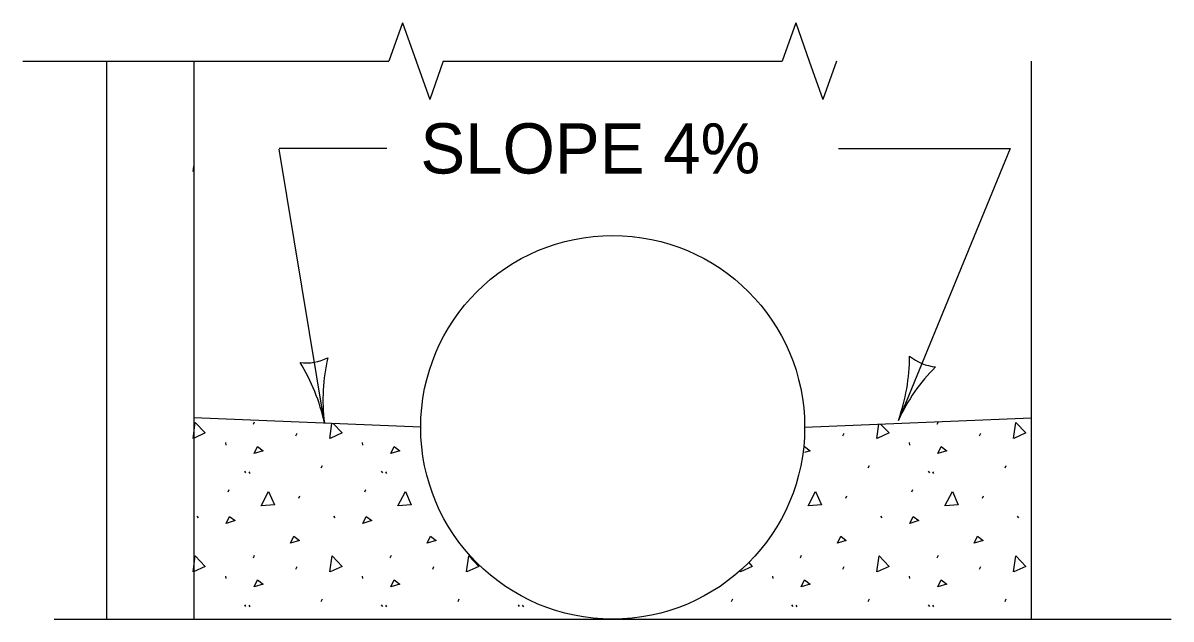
# Model space of a CAD drawing. Extents: x 49991.4 to 50028.3, y 49987.6 to 50011.4.
# Drawn here: x 50019.235 to 50020.605, y 49996.921 to 49997.634 of the extents above; entities that cross this region are included whole.
import ezdxf

# ---------------------------------------------------------------- set-up
doc = ezdxf.new("R2010")
doc.units = 0
for name, color, linetype in [('Level 1', 7, 'Continuous'), ('Level 2', 7, 'Continuous'), ('Level 3', 7, 'Continuous'), ('Level 6', 7, 'Continuous')]:
    doc.layers.add(name, color=color, linetype=linetype)

msp = doc.modelspace()

# ---------------------------------------------------------------- linework, layer by layer
at = {"layer": 'Level 1'}
for p, q in [((50019.3346, 49996.9213), (50019.3346, 49997.588)), ((50019.4387, 49997.588), (50019.4387, 49996.9213)), ((50020.4387, 49996.9213), (50020.4387, 49997.588)), ((50019.7095, 49997.1505), (50019.4387, 49997.1618)), ((50020.1678, 49997.1505), (50020.4387, 49997.1618)), ((50019.5099, 49997.1542), (50019.5112, 49997.1572)), ((50020.3262, 49997.1542), (50020.3276, 49997.1571)), ((50019.5605, 49997.1405), (50019.5618, 49997.1435)), ((50020.2136, 49997.1405), (50020.2149, 49997.1435)), ((50020.3768, 49997.1405), (50020.3782, 49997.1435)), ((50019.4764, 49997.1322), (50019.4768, 49997.1292)), ((50019.6397, 49997.1322), (50019.64, 49997.1292)), ((50020.2928, 49997.1322), (50020.2931, 49997.1292)), ((50019.5908, 49997.1019), (50019.5922, 49997.1049)), ((50020.2439, 49997.1019), (50020.2452, 49997.1049)), ((50020.4072, 49997.1019), (50020.4085, 49997.1049)), ((50019.4992, 49997.098), (50019.5005, 49997.096)), ((50019.5042, 49997.0973), (50019.5056, 49997.0953)), ((50019.6624, 49997.098), (50019.6638, 49997.096)), ((50019.6675, 49997.0973), (50019.6688, 49997.0953)), ((50020.3155, 49997.098), (50020.3168, 49997.096)), ((50020.3206, 49997.0973), (50020.3219, 49997.0953)), ((50019.4795, 49997.0733), (50019.4808, 49997.0763)), ((50019.5638, 49997.0657), (50019.5652, 49997.0687)), ((50019.6428, 49997.0733), (50019.6441, 49997.0763)), ((50020.2169, 49997.0657), (50020.2182, 49997.0687)), ((50020.2958, 49997.0733), (50020.2972, 49997.0763)), ((50020.3802, 49997.0657), (50020.3815, 49997.0687)), ((50019.4422, 49997.0443), (50019.4436, 49997.0423)), ((50019.6055, 49997.0443), (50019.6068, 49997.0423)), ((50020.2586, 49997.0443), (50020.2599, 49997.0423)), ((50020.4218, 49997.0443), (50020.4232, 49997.0423)), ((50019.5099, 49996.9947), (50019.5112, 49996.9977)), ((50019.6732, 49996.9947), (50019.6745, 49996.9977)), ((50020.163, 49996.9947), (50020.1643, 49996.9977)), ((50020.3262, 49996.9947), (50020.3276, 49996.9977)), ((50019.5605, 49996.9811), (50019.5618, 49996.9841)), ((50019.7238, 49996.9811), (50019.7251, 49996.9841)), ((50020.2136, 49996.9811), (50020.2149, 49996.9841)), ((50020.3768, 49996.9811), (50020.3782, 49996.9841)), ((50019.4764, 49996.9727), (50019.4768, 49996.9697)), ((50019.6397, 49996.9727), (50019.64, 49996.9697)), ((50020.1295, 49996.9727), (50020.1298, 49996.9697)), ((50020.2928, 49996.9727), (50020.2931, 49996.9697)), ((50019.5908, 49996.9425), (50019.5922, 49996.9455)), ((50019.7541, 49996.9425), (50019.7554, 49996.9455)), ((50020.0806, 49996.9425), (50020.082, 49996.9455)), ((50020.2439, 49996.9425), (50020.2452, 49996.9455)), ((50020.4072, 49996.9425), (50020.4085, 49996.9455)), ((50019.4992, 49996.9385), (50019.5005, 49996.9365)), ((50019.5042, 49996.9378), (50019.5056, 49996.9358)), ((50019.6624, 49996.9385), (50019.6638, 49996.9365)), ((50019.6675, 49996.9378), (50019.6688, 49996.9358)), ((50019.8257, 49996.9385), (50019.827, 49996.9365)), ((50019.8308, 49996.9378), (50019.8321, 49996.9358)), ((50020.1522, 49996.9385), (50020.1536, 49996.9365)), ((50020.1573, 49996.9378), (50020.1586, 49996.9358)), ((50020.3155, 49996.9385), (50020.3168, 49996.9365)), ((50020.3206, 49996.9378), (50020.3219, 49996.9358)), ((50019.272, 49996.9213), (50020.6053, 49996.9213)), ((50019.272, 49996.9213), (50020.6053, 49996.9213)), ((50019.272, 49996.9213), (50020.6053, 49996.9213))]:
    msp.add_line(p, q, dxfattribs=at)
for points in [[(50019.4378, 49997.456), (50019.4387, 49997.4627)], [(50019.4387, 49997.4564), (50019.4381, 49997.4561)], [(50019.4378, 49997.1371), (50019.4404, 49997.1561), (50019.4523, 49997.1438), (50019.4381, 49997.1372)], [(50019.601, 49997.1371), (50019.6035, 49997.1549)], [(50019.6049, 49997.1549), (50019.6156, 49997.1438), (50019.6014, 49997.1372)], [(50020.2541, 49997.1371), (50020.2564, 49997.1542)], [(50020.2585, 49997.1543), (50020.2686, 49997.1438), (50020.2544, 49997.1372)], [(50020.4174, 49997.1371), (50020.42, 49997.1561), (50020.4319, 49997.1438), (50020.4177, 49997.1372)], [(50019.5106, 49997.1192), (50019.5146, 49997.1275), (50019.5212, 49997.1225), (50019.5106, 49997.1192)], [(50019.6738, 49997.1192), (50019.6778, 49997.1275), (50019.6845, 49997.1225), (50019.6738, 49997.1192)], [(50020.1677, 49997.1275), (50020.1743, 49997.1225), (50020.1677, 49997.1205)], [(50020.3269, 49997.1192), (50020.3309, 49997.1275), (50020.3376, 49997.1225), (50020.3269, 49997.1192)], [(50019.7147, 49997.0987), (50019.7148, 49997.099)], [(50019.7149, 49997.0987), (50019.7147, 49997.0987)], [(50019.5189, 49997.0567), (50019.5279, 49997.0737), (50019.5349, 49997.058), (50019.5192, 49997.0567)], [(50019.6822, 49997.0567), (50019.6912, 49997.0737), (50019.6982, 49997.058), (50019.6825, 49997.0567)], [(50020.172, 49997.0567), (50020.181, 49997.0737), (50020.188, 49997.058), (50020.1723, 49997.0567)], [(50020.3352, 49997.0567), (50020.3442, 49997.0737), (50020.3512, 49997.058), (50020.3356, 49997.0567)], [(50019.4772, 49997.0357), (50019.4812, 49997.044), (50019.4878, 49997.039), (50019.4772, 49997.0357)], [(50019.6404, 49997.0357), (50019.6444, 49997.044), (50019.6511, 49997.039), (50019.6404, 49997.0357)], [(50020.2935, 49997.0357), (50020.2975, 49997.044), (50020.3042, 49997.039), (50020.2935, 49997.0357)], [(50019.5539, 49997.0119), (50019.5579, 49997.0202), (50019.5646, 49997.0152), (50019.5539, 49997.0119)], [(50019.7172, 49997.0119), (50019.7212, 49997.0202), (50019.7278, 49997.0152), (50019.7172, 49997.0119)], [(50020.207, 49997.0119), (50020.211, 49997.0202), (50020.2176, 49997.0152), (50020.207, 49997.0119)], [(50020.3702, 49997.0119), (50020.3742, 49997.0202), (50020.3809, 49997.0152), (50020.3702, 49997.0119)], [(50019.4378, 49996.9776), (50019.4404, 49996.9967), (50019.4523, 49996.9843), (50019.4381, 49996.9777)], [(50019.601, 49996.9776), (50019.6037, 49996.9967), (50019.6156, 49996.9843), (50019.6014, 49996.9777)], [(50019.7643, 49996.9776), (50019.767, 49996.9967), (50019.7789, 49996.9843), (50019.7646, 49996.9777)], [(50020.2541, 49996.9776), (50020.2567, 49996.9967), (50020.2686, 49996.9843), (50020.2544, 49996.9777)], [(50020.4174, 49996.9776), (50020.42, 49996.9967), (50020.4319, 49996.9843), (50020.4177, 49996.9777)], [(50020.1011, 49996.9888), (50020.1054, 49996.9843), (50020.0912, 49996.9777)], [(50019.5106, 49996.9598), (50019.5146, 49996.9681), (50019.5212, 49996.9631), (50019.5106, 49996.9598)], [(50019.6738, 49996.9598), (50019.6778, 49996.9681), (50019.6845, 49996.9631), (50019.6738, 49996.9598)], [(50020.0908, 49996.9776), (50020.091, 49996.9785)], [(50020.1636, 49996.9598), (50020.1676, 49996.9681), (50020.1743, 49996.9631), (50020.1636, 49996.9598)], [(50020.3269, 49996.9598), (50020.3309, 49996.9681), (50020.3376, 49996.9631), (50020.3269, 49996.9598)]]:
    msp.add_lwpolyline(points, dxfattribs=at)
msp.add_ellipse((50019.9387, 49997.1505), major_axis=(0, 0.2292), ratio=0.99996, dxfattribs=at)
at = {"layer": 'Level 3'}
for p, q in [((50019.6691, 49997.4838), (50019.5405, 49997.4838)), ((50019.5948, 49997.1556), (50019.5405, 49997.4829)), ((50020.2084, 49997.4838), (50020.4131, 49997.4838)), ((50020.4131, 49997.4837), (50020.28, 49997.1585))]:
    msp.add_line(p, q, dxfattribs=at)
for centre, radius, start, end in [((50019.5735, 49997.2823), 0.0548, 261.5504, 297.2728), ((50019.8151, 49997.1831), 0.2223, 166.8676, 187.0511), ((50020.0601, 49997.2363), 0.233, 340.5725, 359.8223), ((50020.3284, 49997.2775), 0.0548, 229.884, 265.6064), ((50019.3668, 49997.1064), 0.233, 12.2389, 31.4887), ((50020.4819, 49997.0662), 0.2223, 135.2012, 155.3847)]:
    msp.add_arc(centre, radius, start, end, dxfattribs=at)
at = {"layer": 'Level 6'}
for p, q in [((50019.6878, 49997.6337), (50019.6716, 49997.588)), ((50019.6878, 49997.6337), (50019.704, 49997.588)), ((50020.1572, 49997.6337), (50020.141, 49997.588)), ((50020.1572, 49997.6337), (50020.1734, 49997.588)), ((50019.2346, 49997.588), (50019.6716, 49997.588)), ((50019.704, 49997.588), (50019.7202, 49997.5423)), ((50019.7364, 49997.588), (50019.7202, 49997.5423)), ((50019.7364, 49997.588), (50020.141, 49997.588)), ((50020.1734, 49997.588), (50020.1896, 49997.5423)), ((50020.2058, 49997.588), (50020.1896, 49997.5423))]:
    msp.add_line(p, q, dxfattribs=at)

# ---------------------------------------------------------------- texts
at = {"layer": 'Level 2'}
msp.add_text('SLOPE 4%', height=0.06, dxfattribs=at).set_placement((50019.7091, 49997.4538))

doc.saveas('drawing.dxf')
